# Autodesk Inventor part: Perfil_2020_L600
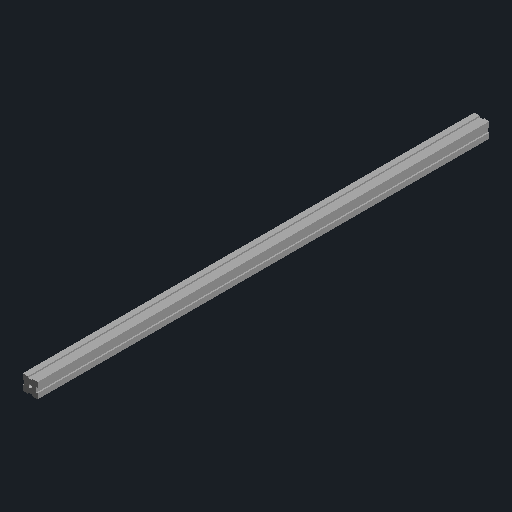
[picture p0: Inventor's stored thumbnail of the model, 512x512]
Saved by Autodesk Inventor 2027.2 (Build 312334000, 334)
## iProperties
Part Number: Perfil_2020_L600
Material: Genérico
Document SubType Name: Modelado
Designer: Usuario
Appearance: Por defecto
Author: Usuario
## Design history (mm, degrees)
sketch "Boceto1"
  geometry: L1 (-10, -10)-(10, -10); L2 (10, -10)-(10, 10); L3 (10, 10)-(-10, 10); L4 (-10, 10)-(-10, -10); L5 (-3, 8.2)-(3, 8.2); L6 (3, 8.2)-(3, 10); L7 (3, 10)-(-3, 10); L8 (-3, 10)-(-3, 8.2); L9 (-3, -10)-(3, -10); L10 (3, -10)-(3, -8.2); L11 (3, -8.2)-(-3, -8.2); L12 (-3, -8.2)-(-3, -10); L13 (8.2, -3)-(10, -3); L14 (10, -3)-(10, 3); L15 (10, 3)-(8.2, 3); L16 (8.2, 3)-(8.2, -3); L17 (-10, -3)-(-8.2, -3); L18 (-8.2, -3)-(-8.2, 3); L19 (-8.2, 3)-(-10, 3); L20 (-10, 3)-(-10, -3); C1 r 2.1 at (0, 0)
  constraints: 40 end point, 10 parallel, 5 horizontal, 5 perpendicular, 1 centre point
extrude "Extrusión1" new body sketch "Boceto1" distance "d0" = 600; taper "d1" = 0 deg
node "Sólido1"
node "Cuerpos sólidos"
node "Cuerpos de superficie"
